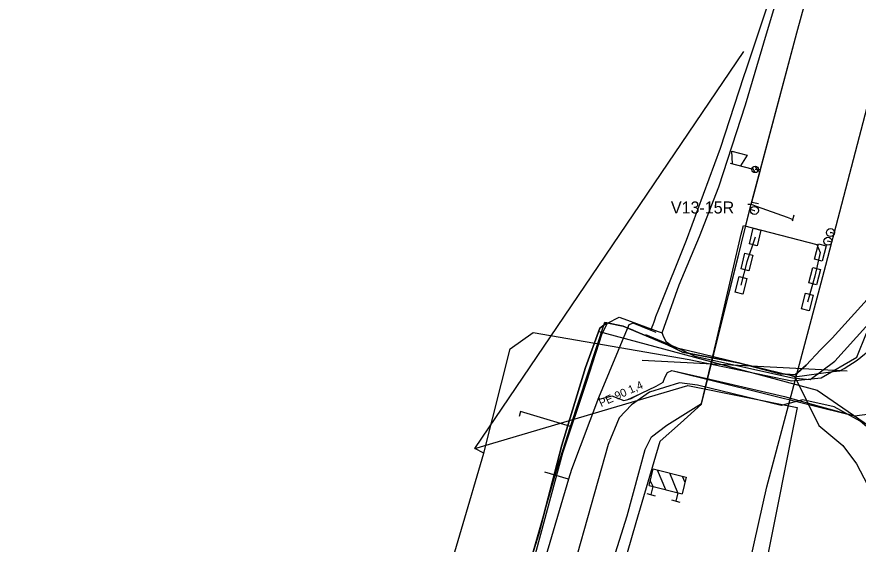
# Model space of a CAD drawing. Extents: x -748507 to -687366, y -1057342 to -1024924.
# Drawn here: x -743353.8 to -743248.5, y -1034581.2 to -1034515.3 of the extents above; entities that cross this region are included whole.
import ezdxf

# ---------------------------------------------------------------- set-up
doc = ezdxf.new("R2010")
doc.units = 0
for name, color, linetype in [('DK + TKK - SŽDC', 7, 'Continuous'), ('PRE - NN', 7, 'Continuous'), ('PRE - OK', 7, 'Continuous'), ('PRE - VN', 7, 'Continuous'), ('Sděl MK - SŽDC', 7, 'Continuous'), ('STL - PRAŽSKÁ PLYNÁRENSKÁ', 7, 'Continuous'), ('SčVK_kanalizace', 7, 'Continuous'), ('SčVK_vodovod', 7, 'Continuous'), ('Telefonica O2', 7, 'Continuous'), ('TK+DOK_Pha Holešovice - Kralupy', 7, 'Continuous'), ('Vedení NN - SŽDC', 7, 'Continuous'), ('Vrstva 15', 7, 'Continuous')]:
    doc.layers.add(name, color=color, linetype=linetype)

msp = doc.modelspace()

# ---------------------------------------------------------------- linework, layer by layer
at = {"layer": 'DK + TKK - SŽDC'}
for p, q in [((-743261.55, -1034539.51), (-743261.45, -1034539.51)), ((-743252.04, -1034542.28), (-743251.94, -1034542.28)), ((-743252.36, -1034543.36), (-743252.26, -1034543.36))]:
    msp.add_line(p, q, dxfattribs=at)
for points in [[(-743261.84, -1034538.46), (-743256.18, -1034517.29), (-743251.9, -1034501.61), (-743245.86, -1034481.26), (-743245.53, -1034480.65), (-743239.89, -1034482.25), (-743235.66, -1034483.63)], [(-743251.53, -1034542.4), (-743246.18, -1034521.96), (-743241.03, -1034504.8), (-743239.25, -1034495.65), (-743233.91, -1034484.65), (-743234.75, -1034484.02), (-743235.66, -1034483.63)], [(-743261.84, -1034538.46), (-743260.98, -1034538.63)], [(-743265.78, -1034554.28), (-743263.12, -1034543.58), (-743262.06, -1034539.33)], [(-743262.33, -1034538.74), (-743261.91, -1034538.73), (-743261.3, -1034538.99), (-743257.42, -1034540.34), (-743256.78, -1034540.6), (-743256.73, -1034540.8)], [(-743262.06, -1034539.33), (-743261.5, -1034539.51)], [(-743256.73, -1034540.8), (-743256.52, -1034540.05)], [(-743257.39, -1034564.51), (-743253.16, -1034548.54), (-743252.58, -1034546.35), (-743251.82, -1034543.49), (-743251.53, -1034542.4)], [(-743251.53, -1034542.4), (-743251.99, -1034542.28)], [(-743251.82, -1034543.49), (-743252.31, -1034543.36)], [(-743285.25, -1034610.91), (-743283.7, -1034604.91), (-743280.81, -1034594.13), (-743276.29, -1034578.55), (-743273.28, -1034568.35), (-743270.77, -1034566.1), (-743268.13, -1034563.75), (-743265.78, -1034554.28)], [(-743262.02, -1034583.38), (-743259.96, -1034574.09), (-743257.39, -1034564.51)]]:
    msp.add_lwpolyline(points, dxfattribs=at)
for centre in [(-743261.5, -1034539.51), (-743251.99, -1034542.28), (-743252.31, -1034543.36)]:
    msp.add_circle(centre, 0.5, dxfattribs=at)
at = {"layer": 'PRE - NN'}
for points in [[(-743275.12, -1034555.03), (-743270.82, -1034556.83), (-743268.97, -1034557.74), (-743256.76, -1034560.46), (-743254.53, -1034560.63), (-743251.44, -1034558.36), (-743242.16, -1034548.04), (-743233.82, -1034538.72), (-743232.65, -1034535.37), (-743229.68, -1034526.89), (-743227.3, -1034520.1), (-743220.12, -1034496.25), (-743217.83, -1034487.97), (-743213.66, -1034474.75), (-743212.88, -1034472.84), (-743209.68, -1034465.05), (-743204.81, -1034455.36), (-743200.32, -1034446.8), (-743198.79, -1034444.04), (-743191.74, -1034431.05), (-743189.38, -1034426.93), (-743187.05, -1034422.46)], [(-743284.5, -1034566.54), (-743280.22, -1034553.49), (-743277.92, -1034553.97), (-743276.65, -1034554.5)], [(-743284.5, -1034566.54), (-743290.77, -1034564.66), (-743290.92, -1034565.29)], [(-743303.07, -1034615.04), (-743298.46, -1034612.89), (-743295.78, -1034604.72), (-743292.59, -1034594.17), (-743286.55, -1034573.02), (-743286.07, -1034571.35), (-743285.82, -1034570.59), (-743284.5, -1034566.54)]]:
    msp.add_lwpolyline(points, dxfattribs=at)
at = {"layer": 'PRE - OK'}
msp.add_lwpolyline([(-743242.25, -1034544.94), (-743251.76, -1034555.48), (-743253.25, -1034556.95), (-743255.05, -1034558.87), (-743256.41, -1034560.07), (-743258.27, -1034559.93), (-743263.49, -1034558.58), (-743270.51, -1034557.21), (-743271.6, -1034556.7), (-743272.36, -1034556.3), (-743277.92, -1034553.97), (-743279.98, -1034553.58), (-743280.84, -1034554.21), (-743282.65, -1034559.13), (-743285.6, -1034568.86), (-743288.46, -1034579.93), (-743289.54, -1034583.42)], dxfattribs=at)
at = {"layer": 'PRE - VN'}
msp.add_lwpolyline([(-743289.54, -1034583.42), (-743288.46, -1034579.93), (-743285.89, -1034569.99), (-743285.6, -1034568.86), (-743282.65, -1034559.13), (-743280.84, -1034554.21), (-743279.98, -1034553.58), (-743277.92, -1034553.97), (-743272.36, -1034556.3), (-743271.6, -1034556.7), (-743270.51, -1034557.21), (-743263.49, -1034558.58), (-743258.27, -1034559.93), (-743256.41, -1034560.07), (-743255.05, -1034558.87), (-743253.25, -1034556.95), (-743251.76, -1034555.48), (-743242.25, -1034544.94)], dxfattribs=at)
at = {"layer": 'Sděl MK - SŽDC'}
for p, q in [((-743264.23, -1034533.68), (-743264.34, -1034532.1)), ((-743264.34, -1034532.1), (-743262.4, -1034532.6)), ((-743262.4, -1034532.6), (-743263.26, -1034533.93)), ((-743264.52, -1034533.61), (-743261.81, -1034534.3)), ((-743261.41, -1034534.78), (-743261.76, -1034534.18)), ((-743261.07, -1034534.57), (-743261.42, -1034533.98))]:
    msp.add_line(p, q, dxfattribs=at)
for points in [[(-743268.89, -1034611.84), (-743268.78, -1034607.9), (-743267.19, -1034604.4), (-743264.3, -1034591.83), (-743262.02, -1034583.38), (-743259.96, -1034574.09), (-743257.39, -1034564.51), (-743253.16, -1034548.54), (-743252.58, -1034546.35), (-743251.82, -1034543.49), (-743251.53, -1034542.4), (-743246.18, -1034521.96), (-743246.2, -1034521.46), (-743241.03, -1034504.8)], [(-743288.28, -1034619.23), (-743287.21, -1034611.85), (-743285.25, -1034610.91), (-743283.7, -1034604.91), (-743280.81, -1034594.13), (-743276.29, -1034578.55), (-743273.28, -1034568.35), (-743270.77, -1034566.1), (-743268.13, -1034563.75), (-743265.78, -1034554.28), (-743263.76, -1034546.18), (-743263.12, -1034543.58), (-743262.06, -1034539.33), (-743261.91, -1034538.73), (-743261.84, -1034538.46), (-743260.73, -1034534.41)], [(-743260.73, -1034534.41), (-743261.42, -1034534.38)]]:
    msp.add_lwpolyline(points, dxfattribs=at)
msp.add_circle((-743261.42, -1034534.38), 0.401, dxfattribs=at)
msp.add_circle((-743261.42, -1034534.38), 0.401, dxfattribs=at)
at = {"layer": 'STL - PRAŽSKÁ PLYNÁRENSKÁ'}
for p, q in [((-743273.83, -1034552.77), (-743273.46, -1034551.84)), ((-743273.93, -1034553.07), (-743273.83, -1034552.77)), ((-743273.79, -1034554.77), (-743274.41, -1034554.52)), ((-743271.84, -1034559.53), (-743248.99, -1034565.21)), ((-743279.33, -1034562.68), (-743277.86, -1034563.28)), ((-743277.32, -1034563.14), (-743275.79, -1034562.45)), ((-743280.99, -1034562.96), (-743280.87, -1034563.12)), ((-743280.87, -1034563.12), (-743280.61, -1034563.03)), ((-743280.61, -1034563.03), (-743280.3, -1034562.96)), ((-743280.3, -1034562.96), (-743280.06, -1034562.89)), ((-743284.75, -1034573.11), (-743287.72, -1034572.24))]:
    msp.add_line(p, q, dxfattribs=at)
for points in [[(-743273.83, -1034552.77), (-743273.46, -1034551.84), (-743270, -1034543.24), (-743265.75, -1034531.72), (-743262.82, -1034522.76), (-743262.5, -1034521.78), (-743259.38, -1034512.39), (-743257.9, -1034507.56), (-743258.79, -1034507.43), (-743258.77, -1034507.23), (-743257.44, -1034502.51), (-743257.41, -1034502.41)], [(-743274.06, -1034553.43), (-743274.01, -1034553.33), (-743273.93, -1034553.07)], [(-743274.41, -1034554.52), (-743276.69, -1034553.59), (-743277.21, -1034553.82), (-743280.99, -1034562.96)], [(-743274.41, -1034554.52), (-743274.29, -1034554.05), (-743274.19, -1034553.77), (-743274.06, -1034553.43)], [(-743280.3, -1034562.96), (-743280.06, -1034562.89), (-743279.33, -1034562.68), (-743277.86, -1034563.28), (-743277.32, -1034563.14), (-743276.92, -1034563.02), (-743276.29, -1034562.68), (-743275.65, -1034562.34), (-743273.8, -1034561.47), (-743272.92, -1034560.98), (-743272.72, -1034560.38), (-743272.39, -1034559.79), (-743271.84, -1034559.53), (-743268.15, -1034560.34), (-743257.74, -1034562.79), (-743253.13, -1034564.06), (-743248.99, -1034565.21), (-743247.06, -1034564.95)], [(-743280.99, -1034562.96), (-743284.39, -1034571.91), (-743284.75, -1034573.11), (-743294.77, -1034607.06), (-743297.13, -1034613.36), (-743301.04, -1034621.39), (-743306.79, -1034632.74), (-743313.1, -1034643.06), (-743327, -1034665.14), (-743349, -1034699.17), (-743354.62, -1034707.84), (-743364.17, -1034722.22), (-743370.88, -1034733.31), (-743371.96, -1034734.74), (-743373.77, -1034737.08), (-743377.3, -1034739.58), (-743378.17, -1034740.1), (-743383.37, -1034743.1), (-743383.84, -1034743.37)]]:
    msp.add_lwpolyline(points, dxfattribs=at)
at = {"layer": 'SčVK_kanalizace'}
for points in [[(-743281.08, -1034554.6), (-743253.64, -1034561.99)], [(-743253.64, -1034561.99), (-743244.56, -1034568.23)]]:
    msp.add_lwpolyline(points, dxfattribs=at)
at = {"layer": 'SčVK_vodovod'}
msp.add_lwpolyline([(-743275.54, -1034558.23), (-743249.89, -1034559.57)], dxfattribs=at)
at = {"layer": 'Telefonica O2'}
for points in [[(-743271.38, -1034550.11), (-743270.92, -1034548.8), (-743268.37, -1034542.76), (-743265.94, -1034536.56), (-743262.61, -1034526.31), (-743259.99, -1034517.42), (-743256.86, -1034507.02), (-743254.65, -1034500), (-743253, -1034494.78), (-743249.71, -1034484.61), (-743245.58, -1034472.74), (-743240.81, -1034460.82), (-743236.72, -1034449.9), (-743232.76, -1034441.18)], [(-743296.48, -1034569.26), (-743262.85, -1034519.63)], [(-743251.64, -1034559.66), (-743250.83, -1034559.58), (-743250.26, -1034559.27), (-743248.64, -1034558.25), (-743246.62, -1034556.55), (-743244.69, -1034554.61), (-743242.96, -1034552.47), (-743241.34, -1034549.95), (-743238.41, -1034545.19), (-743235.68, -1034540.73), (-743235.26, -1034541), (-743231, -1034543.42), (-743230.55, -1034543.64), (-743227.02, -1034534.29)], [(-743273.04, -1034554.83), (-743271.38, -1034550.11)], [(-743298.52, -1034611.85), (-743297.14, -1034608.42), (-743292.31, -1034594), (-743288.76, -1034582.01), (-743285.45, -1034569.81), (-743282.5, -1034560.98), (-743280.57, -1034554.9), (-743279.87, -1034553.62), (-743278.41, -1034552.86), (-743277.85, -1034553.06), (-743273.53, -1034554.65), (-743273.04, -1034554.83)], [(-743277.85, -1034553.06), (-743273.53, -1034554.65)], [(-743295.34, -1034569.86), (-743292.06, -1034556.8), (-743289.18, -1034554.76), (-743269.67, -1034558.14), (-743256.82, -1034560.82), (-743253.14, -1034560.42), (-743248.68, -1034557.84), (-743247.49, -1034554.86)], [(-743256.47, -1034560.3), (-743256.88, -1034560.2), (-743267.99, -1034557.47), (-743271.18, -1034556.72), (-743271.92, -1034556.4), (-743272.49, -1034555.96), (-743272.84, -1034555.37), (-743273.04, -1034554.83)], [(-743256.88, -1034560.2), (-743267.99, -1034557.47)], [(-743256.47, -1034560.3), (-743251.64, -1034559.66)], [(-743256.47, -1034560.3), (-743253.46, -1034566.39), (-743250.43, -1034568.9), (-743248.72, -1034571.21), (-743247.36, -1034573.84)], [(-743237.34, -1034587.18), (-743246.67, -1034567.23), (-743248.26, -1034565.84), (-743251.53, -1034564.06), (-743255.45, -1034563.21), (-743258.18, -1034563.91), (-743268.61, -1034561.37), (-743270.89, -1034561.08), (-743274.61, -1034562.22), (-743276.9, -1034563.81), (-743278.44, -1034565.45), (-743279.78, -1034568.77), (-743284.99, -1034587.1), (-743290.28, -1034604.7), (-743294.12, -1034615.45), (-743298.34, -1034624.19), (-743301.04, -1034629.14), (-743314.56, -1034657.86), (-743319.49, -1034663.3), (-743319.01, -1034664.96), (-743320.86, -1034665.49), (-743329.4, -1034675.81), (-743343.26, -1034696.57), (-743359.5, -1034716.04)], [(-743296.48, -1034569.26), (-743269.82, -1034561.4), (-743256.14, -1034564.14), (-743264.05, -1034603.62), (-743256.46, -1034644.12)], [(-743327.41, -1034660.65), (-743322.5, -1034652.96), (-743314.35, -1034638.88), (-743310.68, -1034626.6), (-743304.99, -1034607.94), (-743300.92, -1034588.88), (-743295.34, -1034569.86)], [(-743295.34, -1034569.86), (-743296.48, -1034569.26)]]:
    msp.add_lwpolyline(points, dxfattribs=at)
at = {"layer": 'TK+DOK_Pha Holešovice - Kralupy'}
for points in [[(-743295.6, -1034642.52), (-743289.66, -1034619.88), (-743287.21, -1034611.85), (-743285.25, -1034610.91), (-743283.7, -1034604.91), (-743280.81, -1034594.13), (-743276.29, -1034578.55), (-743273.28, -1034568.35), (-743270.77, -1034566.1), (-743268.13, -1034563.75), (-743265.78, -1034554.28), (-743263.76, -1034546.18), (-743263.12, -1034543.58), (-743261.91, -1034538.73), (-743256.18, -1034517.29), (-743251.9, -1034501.61)], [(-743285.25, -1034610.91), (-743283.7, -1034604.91), (-743280.81, -1034594.13), (-743276.29, -1034578.55), (-743273.28, -1034568.35), (-743270.77, -1034566.1), (-743268.13, -1034563.75), (-743265.78, -1034554.28), (-743263.76, -1034546.18), (-743263.12, -1034543.58), (-743261.91, -1034538.73), (-743256.18, -1034517.29), (-743251.9, -1034501.61)]]:
    msp.add_lwpolyline(points, dxfattribs=at)
at = {"layer": 'Vedení NN - SŽDC'}
for points in [[(-743287.72, -1034615.2), (-743287.27, -1034610.65), (-743287.49, -1034608.23), (-743287, -1034606.47), (-743281.98, -1034592.1), (-743277.42, -1034577.71), (-743275.17, -1034569.4), (-743274.39, -1034567.83), (-743272.45, -1034566.38), (-743268.12, -1034563.65), (-743266.28, -1034555.99), (-743263.15, -1034542.48), (-743262.87, -1034541.41), (-743253.71, -1034543.75), (-743253.26, -1034544.78), (-743253.96, -1034547.73), (-743254.88, -1034550.96)], [(-743261.16, -1034543.92), (-743262.13, -1034543.68), (-743261.66, -1034541.74), (-743260.69, -1034541.98), (-743261.16, -1034543.92)], [(-743261.41, -1034542.83), (-743262.45, -1034545.95), (-743263.19, -1034548.87)], [(-743253.02, -1034545.87), (-743253.99, -1034545.62), (-743253.5, -1034543.69), (-743252.53, -1034543.94), (-743253.02, -1034545.87)], [(-743262.21, -1034547.04), (-743263.18, -1034546.79), (-743262.69, -1034544.86), (-743261.72, -1034545.11), (-743262.21, -1034547.04)], [(-743253.72, -1034548.82), (-743254.69, -1034548.58), (-743254.2, -1034546.64), (-743253.23, -1034546.89), (-743253.72, -1034548.82)], [(-743262.95, -1034549.96), (-743263.92, -1034549.71), (-743263.43, -1034547.78), (-743262.46, -1034548.03), (-743262.95, -1034549.96)], [(-743254.64, -1034552.05), (-743255.61, -1034551.81), (-743255.12, -1034549.87), (-743254.15, -1034550.11), (-743254.64, -1034552.05)]]:
    msp.add_lwpolyline(points, dxfattribs=at)
at = {"layer": 'Vrstva 15'}
for p, q in [((-743274.69, -1034573.89), (-743274.16, -1034571.82)), ((-743274.16, -1034571.82), (-743270.03, -1034572.88)), ((-743273.65, -1034571.95), (-743272.63, -1034574.42)), ((-743271.08, -1034574.82), (-743272.1, -1034572.35)), ((-743270.03, -1034572.88), (-743270.56, -1034574.95)), ((-743270.55, -1034572.75), (-743270.19, -1034573.5)), ((-743274.69, -1034573.89), (-743270.56, -1034574.95)), ((-743274.18, -1034574.02), (-743274.54, -1034573.27)), ((-743274.44, -1034575.05), (-743274.18, -1034574.02)), ((-743274.18, -1034574.02), (-743274.18, -1034574.02)), ((-743274.96, -1034574.92), (-743273.93, -1034575.18)), ((-743271.08, -1034574.82), (-743271.34, -1034575.85)), ((-743271.86, -1034575.71), (-743270.83, -1034575.98))]:
    msp.add_line(p, q, dxfattribs=at)

# ---------------------------------------------------------------- texts
at = {"layer": 'DK + TKK - SŽDC'}
msp.add_text('V13-15R', height=1.5, dxfattribs=at).set_placement((-743271.95, -1034539.89))
at = {"layer": 'STL - PRAŽSKÁ PLYNÁRENSKÁ'}
msp.add_text('PE 90 1,4', height=1, rotation=24.3448, dxfattribs=at).set_placement((-743280.68, -1034564.11))

doc.saveas('drawing.dxf')
